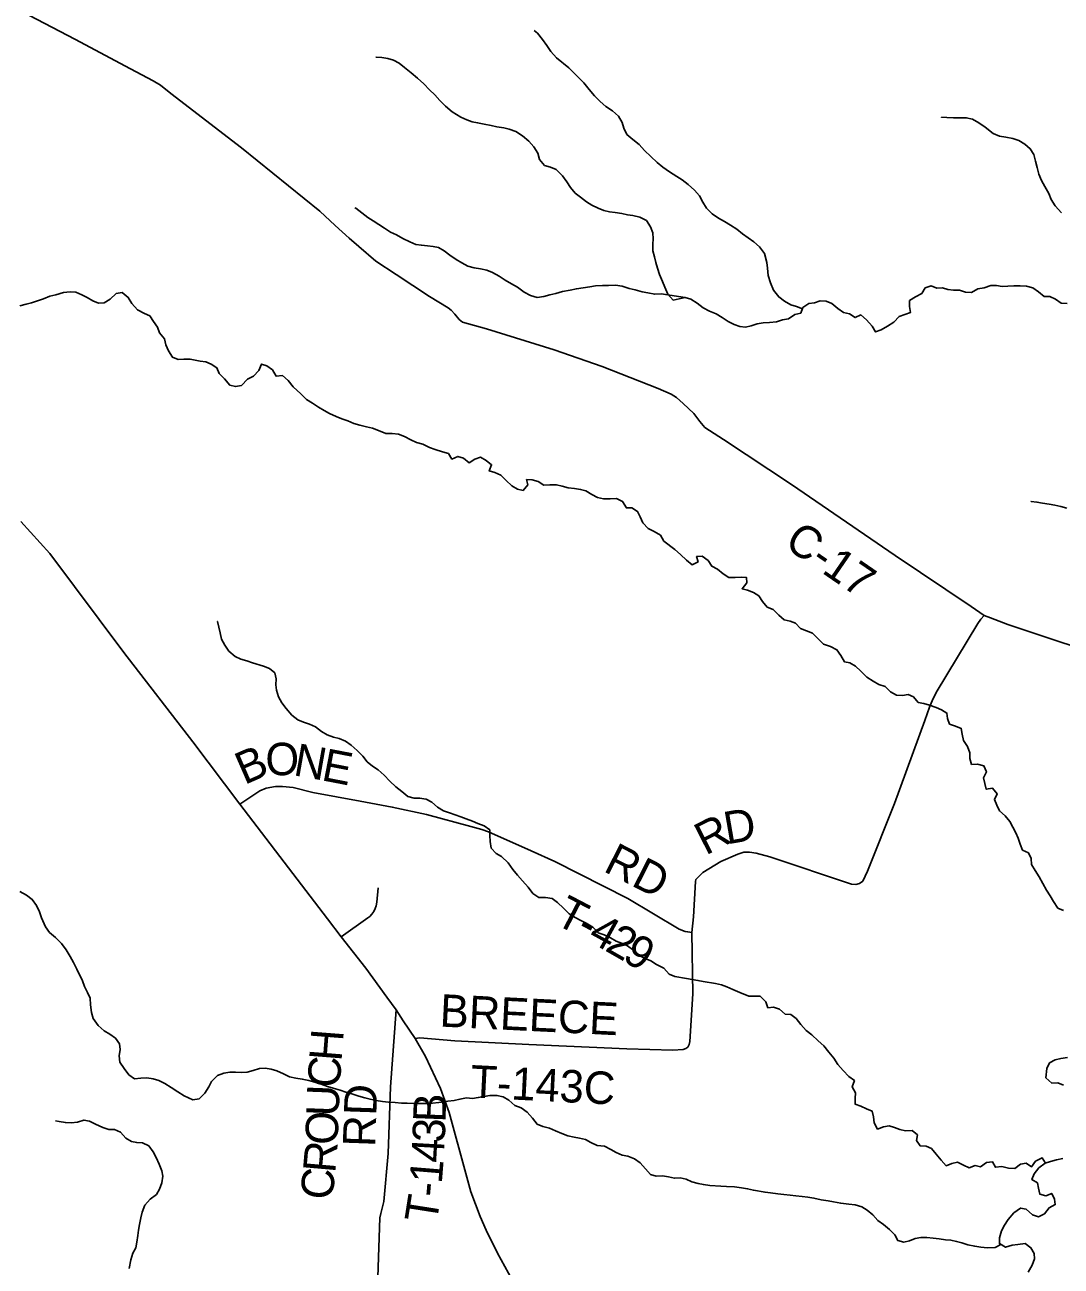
# Model space of a CAD drawing. Extents: x 1759416 to 2214760, y 252598 to 1116833.
# Drawn here: x 1989307 to 1998888, y 845400 to 856869 of the extents above; entities that cross this region are included whole.
import ezdxf

# ---------------------------------------------------------------- set-up
doc = ezdxf.new("R2010")
doc.units = 0
for name, color, linetype in [('GM_X_County_Road', 7, 'Continuous'), ('GM_X_County_Road_Text', 7, 'Continuous'), ('GM_X_Minor_River', 7, 'Continuous'), ('GM_X_State_Route', 7, 'Continuous'), ('GM_X_Township_Road', 7, 'Continuous'), ('GM_X_Township_Road_Text', 7, 'Continuous'), ('GM_X_Township_ROW', 7, 'Continuous')]:
    doc.layers.add(name, color=color, linetype=linetype)

msp = doc.modelspace()

# ---------------------------------------------------------------- linework, layer by layer
at = {"layer": 'GM_X_County_Road'}
msp.add_lwpolyline([(1989345, 856958), (1989777, 856734), (1990232, 856490), (1990493, 856351), (1990560, 856312), (1990656, 856236), (1991310, 855733), (1992034, 855149), (1992176, 855015), (1992305, 854897), (1992394, 854822), (1992551, 854685), (1992739, 854561), (1993049, 854360), (1993222, 854254), (1993248, 854232), (1993283, 854195), (1993323, 854146), (1993352, 854122), (1993574, 854061), (1994202, 853867), (1994644, 853711), (1995162, 853510), (1995282, 853457), (1995331, 853426), (1995393, 853371), (1995492, 853278), (1995547, 853203), (1995594, 853148), (1995767, 853038), (1996395, 852623), (1997353, 851966), (1998054, 851494), (1998175, 851412), (1998233, 851389), (1998394, 851327), (1999461, 850973)], dxfattribs=at)
at = {"layer": 'GM_X_Minor_River'}
for points in [[(1996496, 854246), (1996442, 854266), (1996387, 854283), (1996331, 854315), (1996277, 854356), (1996228, 854418), (1996199, 854486), (1996179, 854554), (1996172, 854620), (1996165, 854674), (1996146, 854756), (1996100, 854818), (1996047, 854863), (1995995, 854901), (1995940, 854938), (1995888, 854982), (1995832, 855019), (1995775, 855051), (1995719, 855084), (1995661, 855124), (1995608, 855176), (1995575, 855231), (1995543, 855289), (1995498, 855341), (1995440, 855394), (1995383, 855436), (1995333, 855469), (1995267, 855511), (1995206, 855554), (1995152, 855596), (1995095, 855652), (1995037, 855707), (1994986, 855765), (1994927, 855810), (1994873, 855856), (1994846, 855916), (1994828, 855968), (1994795, 856025), (1994739, 856075), (1994678, 856116), (1994626, 856160), (1994573, 856212), (1994523, 856273), (1994476, 856333), (1994415, 856393), (1994335, 856472), (1994222, 856563), (1994171, 856623), (1994134, 856678), (1994092, 856734), (1994045, 856792), (1994017, 856816)], [(1995411, 854349), (1995357, 854339), (1995301, 854326), (1995251, 854382), (1995224, 854446), (1995201, 854498), (1995175, 854563), (1995156, 854621), (1995140, 854673), (1995127, 854727), (1995112, 854781), (1995112, 854842), (1995117, 854892), (1995113, 854946), (1995092, 855002), (1995055, 855060), (1994993, 855093), (1994929, 855106), (1994879, 855114), (1994827, 855125), (1994765, 855135), (1994713, 855140), (1994659, 855154), (1994606, 855175), (1994550, 855203), (1994500, 855234), (1994445, 855276), (1994395, 855315), (1994352, 855367), (1994318, 855419), (1994279, 855475), (1994219, 855534), (1994168, 855554), (1994112, 855571), (1994064, 855625), (1994049, 855683), (1994013, 855741), (1993966, 855794), (1993909, 855844), (1993847, 855885), (1993785, 855905), (1993735, 855918), (1993671, 855928), (1993617, 855939), (1993554, 855951), (1993492, 855964), (1993442, 855973), (1993392, 855991), (1993338, 856017), (1993259, 856066), (1993197, 856117), (1993144, 856171), (1993098, 856223), (1993047, 856270), (1992997, 856324), (1992936, 856377), (1992878, 856427), (1992817, 856476), (1992767, 856514), (1992714, 856544), (1992664, 856559), (1992606, 856568), (1992554, 856570), (1992552, 856570)], [(1998889, 855133), (1998833, 855197), (1998796, 855256), (1998772, 855310), (1998737, 855374), (1998706, 855430), (1998682, 855488), (1998665, 855552), (1998650, 855610), (1998636, 855672), (1998601, 855724), (1998551, 855767), (1998496, 855801), (1998440, 855820), (1998376, 855830), (1998318, 855841), (1998258, 855866), (1998185, 855924), (1998127, 855965), (1998068, 855997), (1998010, 856010), (1997956, 856010), (1997892, 856011), (1997832, 856012), (1997782, 856016), (1997782, 856014)], [(1995411, 854349), (1995191, 854383), (1995131, 854380), (1995067, 854392), (1995015, 854403), (1994950, 854421), (1994894, 854434), (1994828, 854454), (1994768, 854463), (1994704, 854462), (1994646, 854460), (1994582, 854457), (1994530, 854449), (1994470, 854440), (1994406, 854431), (1994349, 854419), (1994279, 854404), (1994215, 854387), (1994159, 854375), (1994105, 854360), (1994043, 854351), (1993981, 854369), (1993923, 854400), (1993860, 854444), (1993806, 854475), (1993748, 854509), (1993691, 854546), (1993631, 854582), (1993579, 854601), (1993519, 854615), (1993461, 854624), (1993403, 854640), (1993346, 854669), (1993294, 854701), (1993235, 854742), (1993185, 854782), (1993131, 854811), (1993081, 854821), (1993031, 854826), (1992973, 854832), (1992921, 854841), (1992866, 854863), (1992802, 854896), (1992744, 854930), (1992689, 854955), (1992631, 854989), (1992579, 855024), (1992528, 855058), (1992478, 855089), (1992422, 855131), (1992367, 855174), (1992357, 855178)], [(1990837, 853779), (1990777, 853780), (1990725, 853778), (1990672, 853799), (1990634, 853857), (1990611, 853911), (1990599, 853967), (1990552, 854023), (1990534, 854075), (1990497, 854128), (1990462, 854182), (1990412, 854202), (1990350, 854237), (1990295, 854295), (1990263, 854351), (1990206, 854396), (1990150, 854386), (1990097, 854333), (1990039, 854300), (1989987, 854298), (1989935, 854319), (1989883, 854351), (1989833, 854374), (1989778, 854398), (1989726, 854403), (1989666, 854395), (1989593, 854374), (1989537, 854361), (1989479, 854339), (1989425, 854318), (1989369, 854301), (1989318, 854289), (1989260, 854272)], [(1998944, 854293), (1998886, 854299), (1998836, 854336), (1998782, 854358), (1998730, 854359), (1998677, 854401), (1998625, 854440), (1998567, 854456), (1998507, 854459), (1998451, 854459), (1998395, 854456), (1998343, 854450), (1998289, 854461), (1998237, 854460), (1998177, 854440), (1998117, 854429), (1998060, 854395), (1998002, 854400), (1997949, 854417), (1997893, 854419), (1997841, 854424), (1997789, 854438), (1997737, 854437), (1997687, 854457), (1997631, 854438), (1997598, 854388), (1997540, 854357), (1997485, 854322), (1997485, 854268), (1997496, 854212), (1997442, 854194), (1997390, 854175), (1997339, 854122), (1997283, 854084), (1997224, 854051), (1997172, 854032), (1997139, 854086), (1997087, 854142), (1997034, 854189), (1996982, 854165), (1996932, 854200), (1996876, 854210), (1996822, 854247), (1996767, 854293), (1996715, 854317), (1996661, 854318), (1996607, 854301), (1996555, 854293), (1996500, 854256), (1996480, 854206), (1996426, 854193), (1996367, 854153), (1996311, 854142), (1996255, 854125), (1996191, 854119), (1996133, 854116), (1996077, 854107), (1996022, 854089), (1995970, 854076), (1995916, 854082), (1995863, 854099), (1995809, 854129), (1995755, 854166), (1995698, 854200), (1995638, 854225), (1995578, 854255), (1995521, 854296), (1995465, 854336), (1995411, 854349)], [(1995928, 851766), (1995873, 851763), (1995815, 851762), (1995762, 851796), (1995710, 851840), (1995657, 851867), (1995623, 851919), (1995569, 851961), (1995517, 851958), (1995531, 851906), (1995475, 851879), (1995423, 851923), (1995368, 851974), (1995316, 852020), (1995215, 852099), (1995183, 852153), (1995126, 852189), (1995070, 852216), (1995021, 852268), (1994997, 852322), (1994972, 852374), (1994920, 852407), (1994868, 852405), (1994833, 852466), (1994777, 852494), (1994719, 852489), (1994657, 852491), (1994601, 852502), (1994549, 852530), (1994494, 852563), (1994444, 852577), (1994388, 852584), (1994330, 852592), (1994274, 852607), (1994222, 852618), (1994160, 852618), (1994106, 852615), (1994052, 852649), (1993997, 852664), (1993945, 852668), (1993956, 852618), (1993913, 852567), (1993862, 852579), (1993808, 852610), (1993756, 852658), (1993707, 852709), (1993651, 852733), (1993601, 852748), (1993622, 852805), (1993572, 852844), (1993519, 852874), (1993466, 852857), (1993414, 852823), (1993362, 852864), (1993311, 852882), (1993256, 852857), (1993223, 852909), (1993167, 852924), (1993101, 852944), (1993049, 852963), (1992986, 852995), (1992928, 853010), (1992876, 853036), (1992818, 853065), (1992761, 853087), (1992703, 853092), (1992643, 853094), (1992577, 853121), (1992521, 853144), (1992467, 853154), (1992403, 853169), (1992348, 853187), (1992294, 853210), (1992238, 853230), (1992184, 853249), (1992124, 853277), (1992073, 853306), (1992023, 853338), (1991967, 853373), (1991912, 853407), (1991858, 853461), (1991789, 853524), (1991740, 853584), (1991688, 853629), (1991632, 853623), (1991597, 853680), (1991545, 853720), (1991495, 853734), (1991469, 853675), (1991420, 853622), (1991364, 853596), (1991309, 853537), (1991255, 853527), (1991201, 853540), (1991152, 853598), (1991104, 853649), (1991083, 853701), (1991029, 853733), (1990979, 853754), (1990927, 853762), (1990837, 853779)], [(1998939, 852404), (1998885, 852420), (1998828, 852431), (1998776, 852441), (1998716, 852450), (1998664, 852460), (1998610, 852465), (1998606, 852463)], [(1998909, 848686), (1998858, 848709), (1998816, 848769), (1998785, 848821), (1998753, 848875), (1998718, 848935), (1998683, 848998), (1998647, 849056), (1998614, 849112), (1998609, 849166), (1998585, 849220), (1998531, 849244), (1998508, 849299), (1998489, 849353), (1998467, 849405), (1998440, 849457), (1998412, 849509), (1998369, 849561), (1998317, 849606), (1998292, 849660), (1998270, 849712), (1998295, 849765), (1998253, 849816), (1998195, 849806), (1998182, 849858), (1998170, 849912), (1998197, 849968), (1998174, 850024), (1998114, 850039), (1998060, 850035), (1998042, 850091), (1998043, 850143), (1998021, 850201), (1997984, 850257), (1997971, 850315), (1997963, 850369), (1997911, 850390), (1997856, 850408), (1997836, 850460), (1997831, 850510), (1997781, 850539), (1997731, 850561), (1997671, 850584), (1997618, 850600), (1997566, 850607), (1997522, 850661), (1997472, 850681), (1997420, 850674), (1997366, 850675), (1997309, 850705), (1997259, 850757), (1997203, 850774), (1997148, 850806), (1997092, 850843), (1997037, 850897), (1996985, 850942), (1996935, 850974), (1996883, 850985), (1996850, 851041), (1996815, 851095), (1996755, 851126), (1996689, 851146), (1996642, 851197), (1996588, 851249), (1996532, 851271), (1996479, 851290), (1996431, 851342), (1996381, 851359), (1996327, 851373), (1996276, 851416), (1996226, 851466), (1996171, 851489), (1996127, 851541), (1996092, 851593), (1996042, 851624), (1995988, 851646), (1995938, 851659), (1995983, 851712), (1995979, 851762), (1995928, 851766)], [(1993818, 849065), (1993774, 849125), (1993715, 849184), (1993663, 849212), (1993618, 849263), (1993609, 849323), (1993607, 849379), (1993606, 849430), (1993554, 849467), (1993496, 849491), (1993445, 849512), (1993387, 849534), (1993337, 849551), (1993285, 849569), (1993233, 849588), (1993177, 849608), (1993122, 849641), (1993070, 849687), (1993017, 849714), (1992957, 849724), (1992905, 849725), (1992849, 849739), (1992791, 849784), (1992738, 849830), (1992682, 849881), (1992629, 849935), (1992575, 849985), (1992522, 850020), (1992472, 850060), (1992431, 850113), (1992379, 850165), (1992324, 850215), (1992272, 850250), (1992214, 850274), (1992162, 850289), (1992101, 850309), (1992049, 850340), (1991995, 850382), (1991940, 850407), (1991882, 850425), (1991830, 850448), (1991776, 850492), (1991723, 850551), (1991684, 850605), (1991652, 850659), (1991635, 850721), (1991629, 850771), (1991630, 850825), (1991619, 850881), (1991569, 850923), (1991513, 850944), (1991412, 850975), (1991358, 850993), (1991304, 851008), (1991250, 851032), (1991193, 851083), (1991155, 851137), (1991126, 851193), (1991112, 851251), (1991101, 851303), (1991087, 851355), (1991085, 851355)], [(1998742, 846351), (1998711, 846402), (1998651, 846369), (1998614, 846318), (1998564, 846352), (1998512, 846343), (1998458, 846303), (1998400, 846306), (1998338, 846322), (1998280, 846313), (1998252, 846365), (1998198, 846356), (1998142, 846318), (1998092, 846331), (1998038, 846308), (1997984, 846334), (1997930, 846360), (1997876, 846349), (1997824, 846328), (1997778, 846380), (1997733, 846436), (1997688, 846487), (1997638, 846509), (1997584, 846510), (1997550, 846562), (1997559, 846612), (1997509, 846652), (1997449, 846649), (1997397, 846663), (1997346, 846682), (1997296, 846696), (1997244, 846687), (1997191, 846667), (1997158, 846725), (1997154, 846779), (1997141, 846831), (1997089, 846854), (1997034, 846878), (1996984, 846895), (1996982, 846949), (1996985, 847000), (1996955, 847057), (1996976, 847114), (1996924, 847151), (1996873, 847207), (1996824, 847263), (1996786, 847320), (1996741, 847378), (1996693, 847434), (1996642, 847481), (1996582, 847537), (1996531, 847577), (1996481, 847634), (1996438, 847688), (1996388, 847725), (1996336, 847727), (1996285, 847773), (1996229, 847794), (1996177, 847787), (1996156, 847841), (1996104, 847893), (1996052, 847894), (1996000, 847894), (1995918, 847927), (1995851, 847957), (1995797, 847982), (1995747, 848000), (1995691, 848011), (1995579, 848030), (1995529, 848040), (1995476, 848049), (1995424, 848057), (1995316, 848075), (1995264, 848097), (1995213, 848153), (1995145, 848188), (1995095, 848222), (1995041, 848243), (1994986, 848271), (1994936, 848316), (1994879, 848360), (1994823, 848383), (1994773, 848403), (1994721, 848434), (1994662, 848460), (1994606, 848479), (1994558, 848533), (1994497, 848568), (1994447, 848592), (1994395, 848622), (1994340, 848655), (1994286, 848707), (1994231, 848760), (1994181, 848796), (1994119, 848807), (1994059, 848805), (1994004, 848842), (1993960, 848900), (1993907, 848959), (1993863, 849013), (1993818, 849065)], [(1992555, 846930), (1992499, 846942), (1992449, 846955), (1992395, 846971), (1992329, 846992), (1992275, 847007), (1992221, 847025), (1992158, 847044), (1992104, 847060), (1992046, 847081), (1991996, 847097), (1991932, 847116), (1991872, 847128), (1991811, 847137), (1991753, 847148), (1991697, 847178), (1991637, 847205), (1991585, 847221), (1991529, 847230), (1991477, 847226), (1991417, 847209), (1991361, 847193), (1991309, 847190), (1991255, 847193), (1991203, 847193), (1991147, 847184), (1991089, 847162), (1991034, 847107), (1991007, 847057), (1990971, 846998), (1990918, 846945), (1990860, 846937), (1990780, 846972), (1990721, 847010), (1990659, 847049), (1990602, 847086), (1990546, 847114), (1990494, 847130), (1990436, 847139), (1990378, 847136), (1990320, 847132), (1990270, 847167), (1990225, 847227), (1990186, 847285), (1990180, 847343), (1990187, 847403), (1990181, 847453), (1990144, 847505), (1990094, 847543), (1990039, 847574), (1989985, 847624), (1989938, 847689), (1989922, 847745), (1989913, 847813), (1989910, 847876), (1989886, 847929), (1989859, 847983), (1989839, 848037), (1989789, 848145), (1989757, 848207), (1989726, 848261), (1989690, 848323), (1989647, 848382), (1989592, 848436), (1989534, 848483), (1989497, 848535), (1989462, 848619), (1989442, 848675), (1989415, 848731), (1989375, 848789), (1989324, 848828), (1989262, 848862)], [(1998945, 847327), (1998885, 847318), (1998833, 847307), (1998780, 847277), (1998754, 847226), (1998745, 847140), (1998802, 847090), (1998856, 847095), (1998908, 847073)], [(1998329, 845601), (1998278, 845573), (1998206, 845570), (1998144, 845574), (1998088, 845583), (1998024, 845596), (1997970, 845614), (1997920, 845629), (1997869, 845639), (1997819, 845644), (1997761, 845652), (1997703, 845657), (1997645, 845665), (1997591, 845664), (1997537, 845654), (1997484, 845635), (1997432, 845620), (1997378, 845636), (1997351, 845688), (1997299, 845737), (1997246, 845785), (1997194, 845822), (1997145, 845874), (1997095, 845918), (1997044, 845947), (1996984, 845967), (1996926, 845974), (1996850, 845981), (1996784, 845993), (1996734, 846002), (1996670, 846014), (1996602, 846029), (1996546, 846038), (1996492, 846044), (1996434, 846051), (1996382, 846057), (1996323, 846062), (1996267, 846068), (1996201, 846077), (1996151, 846083), (1996043, 846101), (1995989, 846115), (1995933, 846124), (1995867, 846132), (1995795, 846137), (1995741, 846140), (1995641, 846146), (1995581, 846153), (1995531, 846164), (1995474, 846180), (1995422, 846203), (1995364, 846215), (1995312, 846212), (1995258, 846224), (1995202, 846233), (1995142, 846231), (1995090, 846248), (1995045, 846300), (1994997, 846353), (1994942, 846391), (1994880, 846416), (1994830, 846426), (1994774, 846451), (1994724, 846479), (1994667, 846509), (1994599, 846516), (1994541, 846543), (1994489, 846569), (1994435, 846582), (1994384, 846592), (1994326, 846605), (1994270, 846625), (1994212, 846650), (1994156, 846676), (1994095, 846691), (1994043, 846713), (1993999, 846768), (1993952, 846824), (1993894, 846862), (1993837, 846885), (1993781, 846933), (1993729, 846964), (1993671, 846978), (1993607, 846977), (1993553, 846968), (1993499, 846958), (1993445, 846949), (1993389, 846955), (1993329, 846942), (1993275, 846931), (1993219, 846925), (1993133, 846912), (1993076, 846907), (1993024, 846903), (1992904, 846902), (1992842, 846905), (1992790, 846906), (1992730, 846912), (1992668, 846915), (1992614, 846921), (1992555, 846930)], [(1990271, 845378), (1990286, 845457), (1990307, 845519), (1990333, 845570), (1990344, 845620), (1990352, 845682), (1990357, 845732), (1990366, 845784), (1990380, 845847), (1990393, 845899), (1990417, 845962), (1990466, 846018), (1990523, 846061), (1990551, 846111), (1990574, 846170), (1990582, 846230), (1990573, 846280), (1990548, 846342), (1990520, 846404), (1990495, 846456), (1990453, 846513), (1990396, 846539), (1990342, 846542), (1990292, 846552), (1990242, 846581), (1990193, 846637), (1990137, 846663), (1990085, 846662), (1990029, 846682), (1989959, 846711), (1989904, 846738), (1989854, 846750), (1989795, 846731), (1989735, 846725), (1989683, 846726), (1989625, 846736), (1989590, 846741)], [(1998903, 846394), (1998845, 846383), (1998789, 846368), (1998738, 846350), (1998682, 846309), (1998639, 846254), (1998617, 846200), (1998668, 846169), (1998678, 846119), (1998691, 846064), (1998745, 846049), (1998801, 846072), (1998825, 846020), (1998832, 845968), (1998776, 845939), (1998733, 845882), (1998679, 845854), (1998623, 845873), (1998564, 845925), (1998512, 845936), (1998451, 845892), (1998397, 845831), (1998364, 845778), (1998336, 845726), (1998317, 845662), (1998316, 845609), (1998374, 845574), (1998434, 845593), (1998486, 845599), (1998556, 845608), (1998608, 845570), (1998637, 845518), (1998641, 845468), (1998618, 845410), (1998582, 845345)]]:
    msp.add_lwpolyline(points, dxfattribs=at)
at = {"layer": 'GM_X_State_Route'}
msp.add_lwpolyline([(1993811, 845273), (1993678, 845521), (1993572, 845731), (1993517, 845858), (1993431, 846085), (1993384, 846256), (1993229, 846818), (1993149, 847040), (1993012, 847338), (1992916, 847504), (1992806, 847667), (1992740, 847769), (1992655, 847885), (1992459, 848152), (1992232, 848444), (1992104, 848609), (1991906, 848870), (1991295, 849668), (1990861, 850245), (1990222, 851069), (1989539, 851986), (1989269, 852281)], dxfattribs=at)
at = {"layer": 'GM_X_Township_Road'}
for points in [[(1995472, 848484), (1995488, 848628), (1995507, 848955), (1995510, 848971), (1995524, 848988), (1995576, 849038), (1995740, 849140), (1995897, 849207), (1995953, 849224), (1996005, 849225), (1996069, 849216), (1996194, 849181), (1996950, 848929), (1996988, 848926), (1997024, 848936), (1997054, 848958), (1997097, 849049), (1997347, 849676), (1997626, 850443), (1997671, 850566), (1997694, 850624), (1997733, 850700), (1998116, 851337), (1998145, 851377), (1998175, 851412)], [(1995472, 848484), (1995436, 848488), (1995410, 848493), (1995356, 848513), (1994882, 848798), (1994207, 849140), (1993989, 849238), (1993593, 849412), (1993533, 849435), (1993429, 849463), (1993021, 849572), (1992704, 849642), (1992407, 849697), (1991970, 849777), (1991789, 849822), (1991690, 849831), (1991625, 849833), (1991538, 849816), (1991479, 849793), (1991295, 849668)], [(1992232, 848444), (1992477, 848617), (1992497, 848632), (1992515, 848651), (1992533, 848676), (1992547, 848703), (1992556, 848729), (1992562, 848762), (1992574, 848894)], [(1992916, 847504), (1992960, 847509), (1993283, 847482), (1993967, 847449), (1994872, 847409), (1995297, 847396), (1995392, 847401), (1995417, 847410), (1995435, 847423), (1995448, 847448), (1995456, 847476), (1995481, 847916), (1995472, 848484)], [(1992598, 845886), (1992625, 845997), (1992666, 846440), (1992688, 847056), (1992740, 847769)]]:
    msp.add_lwpolyline(points, dxfattribs=at)
at = {"layer": 'GM_X_Township_ROW'}
msp.add_lwpolyline([(1992530, 844108), (1992588, 845845), (1992598, 845886)], dxfattribs=at)

# ---------------------------------------------------------------- texts
at = {"layer": 'GM_X_County_Road_Text'}
msp.add_text('C-17', height=300, rotation=325.5448, dxfattribs=at).set_placement((1996316, 852052))
at = {"layer": 'GM_X_Township_Road_Text'}
for s, rotation, p in [('B', 23.5702, (1991337, 849844)), ('O', 359.9891, (1991531, 849936)), ('N', 349.964, (1991781, 849937)), ('E', 349.0826, (1992040, 849891)), ('D', 9.8438, (1995797, 849296)), ('R', 27.0067, (1995600, 849192)), ('RD', 332.995, (1994645, 849053)), ('T', 332.5015, (1994193, 848570)), ('-', 332.0979, (1994391, 848467)), ('4', 331.2118, (1994499, 848410)), ('2', 330.1331, (1994660, 848321)), ('9', 329.312, (1994819, 848230)), ('BREECE', 357.1811, (1993138, 847614)), ('H', 85.5585, (1992234, 847287)), ('C', 86.188, (1992218, 847042)), ('T-143C', 357.1274, (1993421, 846959)), ('U', 87.9189, (1992208, 846780)), ('RD', 88.0261, (1992546, 846498)), ('B', 87.8364, (1993195, 846724)), ('O', 87.7894, (1992198, 846516)), ('3', 87.5567, (1993188, 846538)), ('R', 85.0409, (1992176, 846255)), ('4', 86.8595, (1993177, 846350)), ('1', 85.2836, (1993161, 846156)), ('C', 84.0882, (1992150, 846004)), ('-', 84.9129, (1993150, 846032)), ('T', 81.0802, (1993113, 845788))]:
    msp.add_text(s, height=300, rotation=rotation, dxfattribs=at).set_placement(p)

doc.saveas('drawing.dxf')
